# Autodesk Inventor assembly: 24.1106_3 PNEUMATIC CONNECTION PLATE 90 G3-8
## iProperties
Created: 2007-06
Part Number: 24.1106_3 PNEUMATIC CONNECTION PLATE 90 G3-8
Document SubType Name: Assembly
Designer: Andy Moles
Author: Andy Moles
